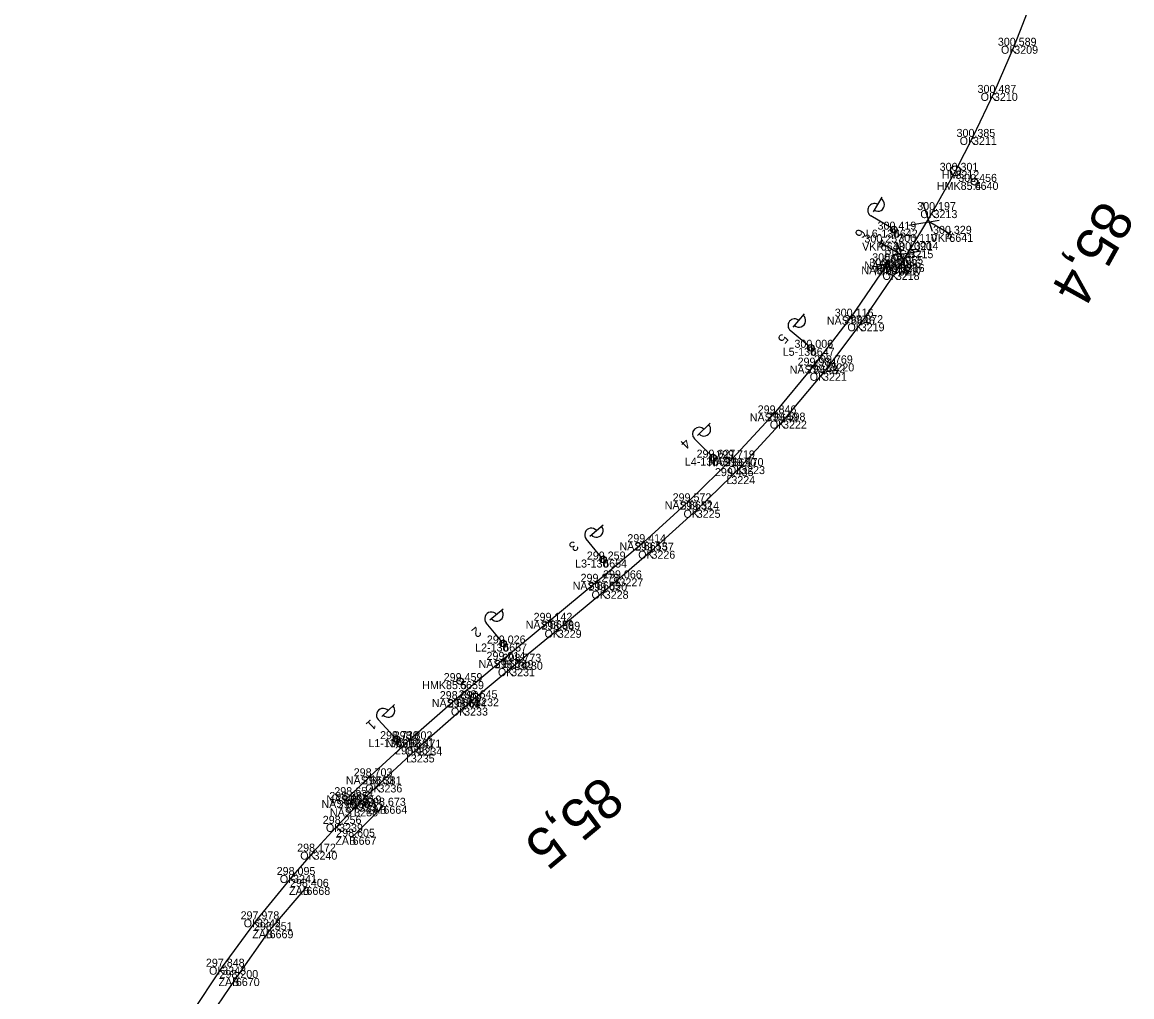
# Model space of a CAD drawing. Extents: x -621782 to -610392, y -1141853 to -1122321.
# Drawn here: x -612970.4 to -612804, y -1134188.8 to -1134042.7 of the extents above; entities that cross this region are included whole.
import ezdxf

# ---------------------------------------------------------------- set-up
doc = ezdxf.new("R2010")
doc.units = 0
for name, color, linetype in [('Vrstva 1', 7, 'Continuous'), ('Vrstva 14', 7, 'Continuous'), ('Vrstva 17', 7, 'Continuous'), ('Vrstva 25', 7, 'Continuous'), ('Vrstva 4', 7, 'Continuous'), ('Vrstva 60', 7, 'Continuous'), ('Vrstva 61', 7, 'Continuous'), ('Vrstva 62', 7, 'Continuous'), ('Vrstva 7', 7, 'Continuous')]:
    doc.layers.add(name, color=color, linetype=linetype)

msp = doc.modelspace()

# ---------------------------------------------------------------- linework, layer by layer
at = {"layer": 'Vrstva 1'}
msp.add_lwpolyline([(-612818.93, -1134039.12), (-612821.66, -1134046.19), (-612824.71, -1134053.26), (-612827.85, -1134059.86), (-612830.48, -1134064.94), (-612833.76, -1134070.83), (-612836.59, -1134075.6), (-612837.36, -1134076.84), (-612838.67, -1134078.92), (-612838.99, -1134079.43), (-612839.42, -1134080.1), (-612844.68, -1134087.78), (-612849.22, -1134093.81), (-612850.33, -1134095.22), (-612856.32, -1134102.39), (-612862.6, -1134109.21), (-612864.07, -1134110.71), (-612869.26, -1134115.76), (-612876.05, -1134121.9), (-612880.84, -1134126.04), (-612883.05, -1134127.9), (-612890.09, -1134133.75), (-612895.91, -1134138.55), (-612897.08, -1134139.51), (-612902.48, -1134144.02), (-612904.13, -1134145.42), (-612910.98, -1134151.41), (-612912.12, -1134152.44), (-612916.97, -1134156.94), (-612919.88, -1134159.8), (-612920.61, -1134160.53), (-612922.87, -1134162.85), (-612926.71, -1134167.02), (-612929.78, -1134170.52), (-612935.18, -1134177.16), (-612940.39, -1134184.27), (-612945.23, -1134191.6)], dxfattribs=at)
at = {"layer": 'Vrstva 14'}
msp.add_lwpolyline([(-612840.5, -1134078.51), (-612840.94, -1134079.27), (-612846.12, -1134086.81), (-612851.69, -1134094.15), (-612857.67, -1134101.31), (-612863.9, -1134108.06), (-612870.43, -1134114.49), (-612877.21, -1134120.62), (-612884.22, -1134126.56), (-612891.26, -1134132.41), (-612898.32, -1134138.26), (-612905.33, -1134144.15), (-612912.24, -1134150.18), (-612918.22, -1134155.72), (-612921.14, -1134158.55), (-612921.89, -1134159.27)], dxfattribs=at)
at = {"layer": 'Vrstva 17'}
msp.add_line((-612916.23, -1134160.14), (-612920.84, -1134164.79), dxfattribs=at)
msp.add_lwpolyline([(-612927.77, -1134172.3), (-612933.29, -1134178.8), (-612938.35, -1134185.97), (-612943.09, -1134192.98), (-612947.84, -1134200.71), (-612952.1, -1134209.25), (-612959.02, -1134224.6), (-612961.12, -1134230.38), (-612963.84, -1134239.1), (-612966.16, -1134247.97), (-612967.73, -1134256.35), (-612969.08, -1134264.94), (-612969.78, -1134271.48), (-612970.38, -1134281.21), (-612970.31, -1134291.21), (-612969.72, -1134300.18), (-612969.16, -1134308.74)], dxfattribs=at)
at = {"layer": 'Vrstva 25'}
for p, q in [((-612842.78, -1134071.11), (-612841.45, -1134068.88)), ((-612840.13, -1134073.5), (-612843.14, -1134071.71)), ((-612839.82, -1134074.24), (-612840.04, -1134073.39)), ((-612839.45, -1134074.19), (-612839.68, -1134073.26)), ((-612854.78, -1134088.37), (-612853.11, -1134086.37)), ((-612852.54, -1134091.15), (-612855.23, -1134088.9)), ((-612852.35, -1134091.93), (-612852.43, -1134091.05)), ((-612851.97, -1134091.93), (-612852.06, -1134090.98)), ((-612869.12, -1134104.6), (-612867.25, -1134102.78)), ((-612867.17, -1134107.59), (-612869.62, -1134105.09)), ((-612867.07, -1134108.39), (-612867.05, -1134107.51)), ((-612866.69, -1134108.43), (-612866.68, -1134107.47)), ((-612885.29, -1134119.7), (-612883.29, -1134118.04)), ((-612883.59, -1134122.84), (-612885.83, -1134120.14)), ((-612883.55, -1134123.64), (-612883.47, -1134122.76)), ((-612883.18, -1134123.71), (-612883.09, -1134122.76)), ((-612900.27, -1134132.28), (-612898.26, -1134130.62)), ((-612898.58, -1134135.42), (-612900.81, -1134132.72)), ((-612898.54, -1134136.23), (-612898.46, -1134135.35)), ((-612898.17, -1134136.3), (-612898.08, -1134135.35)), ((-612916.48, -1134146.74), (-612914.58, -1134144.97)), ((-612914.62, -1134149.78), (-612917, -1134147.22)), ((-612914.53, -1134150.58), (-612914.49, -1134149.7)), ((-612914.15, -1134150.63), (-612914.12, -1134149.67))]:
    msp.add_line(p, q, dxfattribs=at)
for centre in [(-612839.7, -1134073.76), (-612852.16, -1134091.47), (-612866.83, -1134107.95), (-612883.28, -1134123.22), (-612898.27, -1134135.81), (-612914.28, -1134150.15)]:
    msp.add_circle(centre, 0.5, dxfattribs=at)
for centre, start, end in [((-612842.63, -1134070.85), 59.2506, 239.2506), ((-612842.11, -1134070), 238.548, 59.9532), ((-612853.93, -1134087.38), 229.4274, 50.8326), ((-612854.58, -1134088.14), 50.13, 230.13), ((-612868.9, -1134104.39), 44.2442, 224.2442), ((-612868.18, -1134103.7), 223.5416, 44.9467), ((-612885.06, -1134119.51), 39.6982, 219.6982), ((-612884.28, -1134118.88), 218.9956, 40.4007), ((-612900.04, -1134132.09), 39.479, 219.479), ((-612899.26, -1134131.46), 218.7764, 40.1816), ((-612915.52, -1134145.86), 222.1786, 43.5837), ((-612916.27, -1134146.54), 42.8812, 222.8812)]:
    msp.add_arc(centre, 1, start, end, dxfattribs=at)
at = {"layer": 'Vrstva 4'}
for p, q in [((-612833.92, -1134074.04), (-612835.39, -1134069.68)), ((-612837.44, -1134073.11), (-612832.9, -1134072.33)), ((-612831.39, -1134074.39), (-612834.41, -1134072.59)), ((-612841.41, -1134075.27), (-612841.92, -1134076.13)), ((-612831.64, -1134074.82), (-612831.13, -1134073.96)), ((-612841.67, -1134075.7), (-612838.64, -1134077.5)), ((-612835.61, -1134076.97), (-612840.16, -1134077.76)), ((-612839.13, -1134076.04), (-612837.66, -1134080.41)), ((-612838.67, -1134078.92), (-612837.36, -1134076.84))]:
    msp.add_line(p, q, dxfattribs=at)
at = {"layer": 'Vrstva 60'}
for p, q in [((-612821.66, -1134046.19), (-612821.66, -1134046.19)), ((-612824.71, -1134053.26), (-612824.71, -1134053.26)), ((-612827.85, -1134059.86), (-612827.85, -1134059.86)), ((-612830.48, -1134064.94), (-612830.48, -1134064.94)), ((-612827.6, -1134066.6), (-612827.6, -1134066.6)), ((-612833.76, -1134070.83), (-612833.76, -1134070.83)), ((-612839.7, -1134073.76), (-612839.7, -1134073.76)), ((-612831.39, -1134074.39), (-612831.39, -1134074.39)), ((-612841.67, -1134075.7), (-612841.67, -1134075.7)), ((-612837.36, -1134076.84), (-612837.36, -1134076.84)), ((-612836.59, -1134075.6), (-612836.59, -1134075.6)), ((-612840.5, -1134078.51), (-612840.5, -1134078.51)), ((-612840.94, -1134079.27), (-612840.94, -1134079.27)), ((-612839.42, -1134080.1), (-612839.42, -1134080.1)), ((-612838.99, -1134079.43), (-612838.99, -1134079.43)), ((-612838.67, -1134078.92), (-612838.67, -1134078.92)), ((-612846.12, -1134086.81), (-612846.12, -1134086.81)), ((-612844.68, -1134087.78), (-612844.68, -1134087.78)), ((-612852.16, -1134091.47), (-612852.16, -1134091.47)), ((-612851.69, -1134094.15), (-612851.69, -1134094.15)), ((-612850.33, -1134095.22), (-612850.33, -1134095.22)), ((-612849.22, -1134093.81), (-612849.22, -1134093.81)), ((-612857.67, -1134101.31), (-612857.67, -1134101.31)), ((-612856.32, -1134102.39), (-612856.32, -1134102.39)), ((-612866.83, -1134107.95), (-612866.83, -1134107.95)), ((-612863.9, -1134108.06), (-612863.9, -1134108.06)), ((-612862.6, -1134109.21), (-612862.6, -1134109.21)), ((-612864.07, -1134110.71), (-612864.07, -1134110.71)), ((-612870.43, -1134114.49), (-612870.43, -1134114.49)), ((-612869.26, -1134115.76), (-612869.26, -1134115.76)), ((-612877.21, -1134120.62), (-612877.21, -1134120.62)), ((-612876.05, -1134121.9), (-612876.05, -1134121.9)), ((-612883.28, -1134123.22), (-612883.28, -1134123.22)), ((-612884.22, -1134126.56), (-612884.22, -1134126.56)), ((-612880.84, -1134126.04), (-612880.84, -1134126.04)), ((-612883.05, -1134127.9), (-612883.05, -1134127.9)), ((-612891.26, -1134132.41), (-612891.26, -1134132.41)), ((-612890.09, -1134133.75), (-612890.09, -1134133.75)), ((-612898.27, -1134135.81), (-612898.27, -1134135.81)), ((-612898.32, -1134138.26), (-612898.32, -1134138.26)), ((-612895.91, -1134138.55), (-612895.91, -1134138.55)), ((-612897.08, -1134139.51), (-612897.08, -1134139.51)), ((-612904.73, -1134141.45), (-612904.73, -1134141.45)), ((-612905.33, -1134144.15), (-612905.33, -1134144.15)), ((-612902.48, -1134144.02), (-612902.48, -1134144.02)), ((-612904.13, -1134145.42), (-612904.13, -1134145.42)), ((-612914.28, -1134150.15), (-612914.28, -1134150.15)), ((-612912.24, -1134150.18), (-612912.24, -1134150.18)), ((-612910.98, -1134151.41), (-612910.98, -1134151.41)), ((-612912.12, -1134152.44), (-612912.12, -1134152.44)), ((-612918.22, -1134155.72), (-612918.22, -1134155.72)), ((-612921.14, -1134158.55), (-612921.14, -1134158.55)), ((-612916.97, -1134156.94), (-612916.97, -1134156.94)), ((-612921.89, -1134159.27), (-612921.89, -1134159.27)), ((-612919.88, -1134159.8), (-612919.88, -1134159.8)), ((-612916.23, -1134160.14), (-612916.23, -1134160.14)), ((-612920.61, -1134160.53), (-612920.61, -1134160.53)), ((-612922.87, -1134162.85), (-612922.87, -1134162.85)), ((-612920.84, -1134164.79), (-612920.84, -1134164.79)), ((-612926.71, -1134167.02), (-612926.71, -1134167.02)), ((-612929.78, -1134170.52), (-612929.78, -1134170.52)), ((-612927.77, -1134172.3), (-612927.77, -1134172.3)), ((-612935.18, -1134177.16), (-612935.18, -1134177.16)), ((-612933.29, -1134178.8), (-612933.29, -1134178.8)), ((-612940.39, -1134184.27), (-612940.39, -1134184.27)), ((-612938.35, -1134185.97), (-612938.35, -1134185.97))]:
    msp.add_line(p, q, dxfattribs=at)
at = {"layer": 'Vrstva 7'}
for p, q in [((-612827.58, -1134066.56), (-612827.63, -1134066.64)), ((-612904.69, -1134141.42), (-612904.77, -1134141.49))]:
    msp.add_line(p, q, dxfattribs=at)
for centre, radius in [((-612830.48, -1134064.94), 0.75), ((-612827.6, -1134066.6), 0.5), ((-612904.73, -1134141.45), 0.5), ((-612902.48, -1134144.02), 0.75)]:
    msp.add_circle(centre, radius, dxfattribs=at)

# ---------------------------------------------------------------- texts
at = {"layer": 'Vrstva 25'}
for s, rotation, p in [('6', 239.2506, (-612845.09, -1134073.49)), ('5', 230.13, (-612856.53, -1134089.23)), ('4', 224.2442, (-612871.05, -1134104.96)), ('3', 219.6982, (-612887.74, -1134120.31)), ('2', 219.479, (-612902.31, -1134133.19)), ('1', 222.8812, (-612918.13, -1134147.11))]:
    msp.add_text(s, height=1.5, rotation=rotation, dxfattribs=at).set_placement(p)
at = {"layer": 'Vrstva 60'}
for s, p in [('3209', (-612821.66, -1134047.39)), ('3210', (-612824.71, -1134054.46)), ('3211', (-612827.85, -1134061.06)), ('3212', (-612830.48, -1134066.14)), ('6640', (-612827.6, -1134067.8)), ('3213', (-612833.76, -1134072.03)), ('6642', (-612839.7, -1134074.96)), ('6641', (-612831.39, -1134075.59)), ('6643', (-612841.67, -1134076.9)), ('3215', (-612837.36, -1134078.04)), ('3214', (-612836.59, -1134076.8)), ('6644', (-612840.5, -1134079.71)), ('6645', (-612840.94, -1134080.47)), ('3218', (-612839.42, -1134081.3)), ('3217', (-612838.99, -1134080.63)), ('3216', (-612838.67, -1134080.12)), ('6646', (-612846.12, -1134088.01)), ('3219', (-612844.68, -1134088.99)), ('6647', (-612852.16, -1134092.67)), ('6648', (-612851.69, -1134095.35)), ('3221', (-612850.33, -1134096.42)), ('3220', (-612849.22, -1134095.01)), ('6649', (-612857.67, -1134102.51)), ('3222', (-612856.32, -1134103.59)), ('6651', (-612866.83, -1134109.15)), ('6650', (-612863.9, -1134109.26)), ('3223', (-612862.6, -1134110.41)), ('3224', (-612864.07, -1134111.91)), ('6652', (-612870.43, -1134115.69)), ('3225', (-612869.26, -1134116.96)), ('6653', (-612877.21, -1134121.82)), ('3226', (-612876.05, -1134123.1)), ('6654', (-612883.28, -1134124.42)), ('6655', (-612884.22, -1134127.76)), ('3227', (-612880.84, -1134127.24)), ('3228', (-612883.05, -1134129.1)), ('6656', (-612891.26, -1134133.6)), ('3229', (-612890.09, -1134134.95)), ('6657', (-612898.27, -1134137.01)), ('6658', (-612898.32, -1134139.46)), ('3230', (-612895.91, -1134139.75)), ('3231', (-612897.08, -1134140.71)), ('6659', (-612904.73, -1134142.65)), ('6660', (-612905.33, -1134145.34)), ('3232', (-612902.48, -1134145.22)), ('3233', (-612904.13, -1134146.62)), ('6662', (-612914.28, -1134151.35)), ('6661', (-612912.24, -1134151.38)), ('3234', (-612910.98, -1134152.61)), ('3235', (-612912.12, -1134153.64)), ('6663', (-612918.22, -1134156.92)), ('6665', (-612921.14, -1134159.75)), ('3236', (-612916.97, -1134158.14)), ('6666', (-612921.89, -1134160.47)), ('3237', (-612919.88, -1134161)), ('6664', (-612916.23, -1134161.34)), ('3238', (-612920.61, -1134161.73)), ('3239', (-612922.87, -1134164.05)), ('6667', (-612920.84, -1134165.99)), ('3240', (-612926.71, -1134168.22)), ('3241', (-612929.78, -1134171.72)), ('6668', (-612927.77, -1134173.5)), ('3242', (-612935.18, -1134178.36)), ('6669', (-612933.29, -1134180)), ('3243', (-612940.39, -1134185.47)), ('6670', (-612938.35, -1134187.17))]:
    msp.add_text(s, height=1.2, dxfattribs=at).set_placement(p)
at = {"layer": 'Vrstva 61'}
for s, p in [('300.589', (-612824.12, -1134046.19)), ('300.487', (-612827.16, -1134053.26)), ('300.385', (-612830.31, -1134059.86)), ('300.301', (-612832.84, -1134064.94)), ('300.456', (-612830.05, -1134066.6)), ('300.197', (-612836.21, -1134070.83)), ('300.419', (-612842.15, -1134073.76)), ('300.329', (-612833.84, -1134074.39)), ('300.257', (-612844.12, -1134075.7)), ('300.110', (-612839.04, -1134075.6)), ('300.090', (-612839.81, -1134076.84)), ('300.310', (-612843.39, -1134079.27)), ('300.083', (-612842.95, -1134078.51)), ('300.046', (-612841.45, -1134079.43)), ('300.055', (-612841.13, -1134078.92)), ('300.033', (-612841.87, -1134080.1)), ('300.116', (-612848.57, -1134086.81)), ('299.872', (-612847.13, -1134087.78)), ('300.006', (-612854.61, -1134091.47)), ('299.984', (-612854.14, -1134094.15)), ('299.769', (-612851.67, -1134093.81)), ('299.742', (-612852.78, -1134095.22)), ('299.846', (-612860.12, -1134101.31)), ('299.598', (-612858.77, -1134102.39)), ('299.627', (-612869.28, -1134107.95)), ('299.719', (-612866.35, -1134108.06)), ('299.470', (-612865.05, -1134109.21)), ('299.435', (-612866.53, -1134110.71)), ('299.572', (-612872.87, -1134114.49)), ('299.314', (-612871.71, -1134115.76)), ('299.414', (-612879.66, -1134120.62)), ('299.157', (-612878.5, -1134121.9)), ('299.259', (-612885.73, -1134123.22)), ('299.066', (-612883.3, -1134126.04)), ('299.278', (-612886.67, -1134126.56)), ('299.020', (-612885.5, -1134127.9)), ('299.142', (-612893.71, -1134132.41)), ('298.889', (-612892.54, -1134133.75)), ('299.026', (-612900.72, -1134135.81)), ('299.014', (-612900.77, -1134138.26)), ('298.749', (-612899.53, -1134139.51)), ('298.773', (-612898.37, -1134138.55)), ('299.459', (-612907.19, -1134141.45)), ('298.890', (-612907.78, -1134144.15)), ('298.645', (-612904.94, -1134144.02)), ('298.614', (-612906.58, -1134145.42)), ('298.730', (-612916.73, -1134150.15)), ('298.802', (-612914.69, -1134150.18)), ('298.471', (-612913.34, -1134151.41)), ('298.461', (-612914.48, -1134152.44)), ('298.703', (-612920.68, -1134155.72)), ('298.381', (-612919.32, -1134156.94)), ('298.385', (-612924.34, -1134159.27)), ('298.654', (-612923.59, -1134158.55)), ('298.304', (-612923.06, -1134160.53)), ('298.319', (-612922.33, -1134159.8)), ('298.673', (-612918.68, -1134160.14)), ('298.256', (-612925.32, -1134162.85)), ('298.605', (-612923.3, -1134164.79)), ('298.172', (-612929.16, -1134167.02)), ('298.095', (-612932.23, -1134170.52)), ('298.406', (-612930.23, -1134172.3)), ('297.978', (-612937.64, -1134177.16)), ('298.351', (-612935.64, -1134178.8)), ('297.848', (-612942.84, -1134184.27)), ('298.200', (-612940.8, -1134185.97))]:
    msp.add_text(s, height=1.2, dxfattribs=at).set_placement(p)
at = {"layer": 'Vrstva 62'}
for s, p in [('OK', (-612823.65, -1134047.39)), ('OK', (-612826.7, -1134054.46)), ('OK', (-612829.84, -1134061.06)), ('HM', (-612832.52, -1134066.14)), ('HMK85.4', (-612833.26, -1134067.8)), ('OK', (-612835.74, -1134072.03)), ('L6-130', (-612843.91, -1134074.96)), ('VKR', (-612834.19, -1134075.59)), ('VKR', (-612844.47, -1134076.9)), ('PRCH', (-612841.14, -1134078.04)), ('L', (-612837.3, -1134076.8)), ('NAST', (-612844.14, -1134079.71)), ('NAST', (-612844.58, -1134080.47)), ('NAST', (-612842.63, -1134080.63)), ('PRCH', (-612842.45, -1134080.12)), ('OK', (-612841.41, -1134081.3)), ('NAST', (-612849.76, -1134088.01)), ('OK', (-612846.67, -1134088.99)), ('L5-130', (-612856.37, -1134092.67)), ('NAST', (-612855.33, -1134095.35)), ('OK', (-612852.32, -1134096.42)), ('L', (-612849.93, -1134095.01)), ('NAST', (-612861.31, -1134102.51)), ('OK', (-612858.3, -1134103.59)), ('L4-130', (-612871.04, -1134109.15)), ('NAST', (-612867.54, -1134109.26)), ('OK', (-612864.59, -1134110.41)), ('L', (-612864.79, -1134111.91)), ('NAST', (-612874.06, -1134115.69)), ('OK', (-612871.24, -1134116.96)), ('NAST', (-612880.85, -1134121.82)), ('OK', (-612878.03, -1134123.1)), ('L3-130', (-612887.49, -1134124.42)), ('NAST', (-612887.86, -1134127.76)), ('L', (-612881.56, -1134127.24)), ('OK', (-612885.03, -1134129.1)), ('NAST', (-612894.9, -1134133.6)), ('OK', (-612892.07, -1134134.95)), ('L2-130', (-612902.48, -1134137.01)), ('NAST', (-612901.96, -1134139.46)), ('L', (-612896.63, -1134139.75)), ('OK', (-612899.06, -1134140.71)), ('HMK85.5', (-612910.41, -1134142.65)), ('NAST', (-612908.97, -1134145.34)), ('HM', (-612904.52, -1134145.22)), ('OK', (-612906.11, -1134146.62)), ('L1-130', (-612918.49, -1134151.35)), ('NAST', (-612915.88, -1134151.38)), ('OK', (-612912.97, -1134152.61)), ('L', (-612912.83, -1134153.64)), ('NAST', (-612921.86, -1134156.92)), ('NAST', (-612924.78, -1134159.75)), ('OK', (-612918.95, -1134158.14)), ('NAST', (-612925.52, -1134160.47)), ('OK', (-612921.87, -1134161)), ('ZAB', (-612918.83, -1134161.34)), ('NAST', (-612924.25, -1134161.73)), ('OK', (-612924.85, -1134164.05)), ('ZAB', (-612923.44, -1134165.99)), ('OK', (-612928.7, -1134168.22)), ('OK', (-612931.76, -1134171.72)), ('ZAB', (-612930.38, -1134173.5)), ('OK', (-612937.17, -1134178.36)), ('ZAB', (-612935.89, -1134180)), ('OK', (-612942.37, -1134185.47)), ('ZAB', (-612940.95, -1134187.17))]:
    msp.add_text(s, height=1.2, dxfattribs=at).set_placement(p)
at = {"layer": 'Vrstva 7'}
for s, rotation, p in [('85,4', 240.9437, (-612808.67, -1134069.09)), ('85,5', 219.8785, (-612883.5, -1134155.43))]:
    msp.add_text(s, height=6, rotation=rotation, dxfattribs=at).set_placement(p)

doc.saveas('drawing.dxf')
